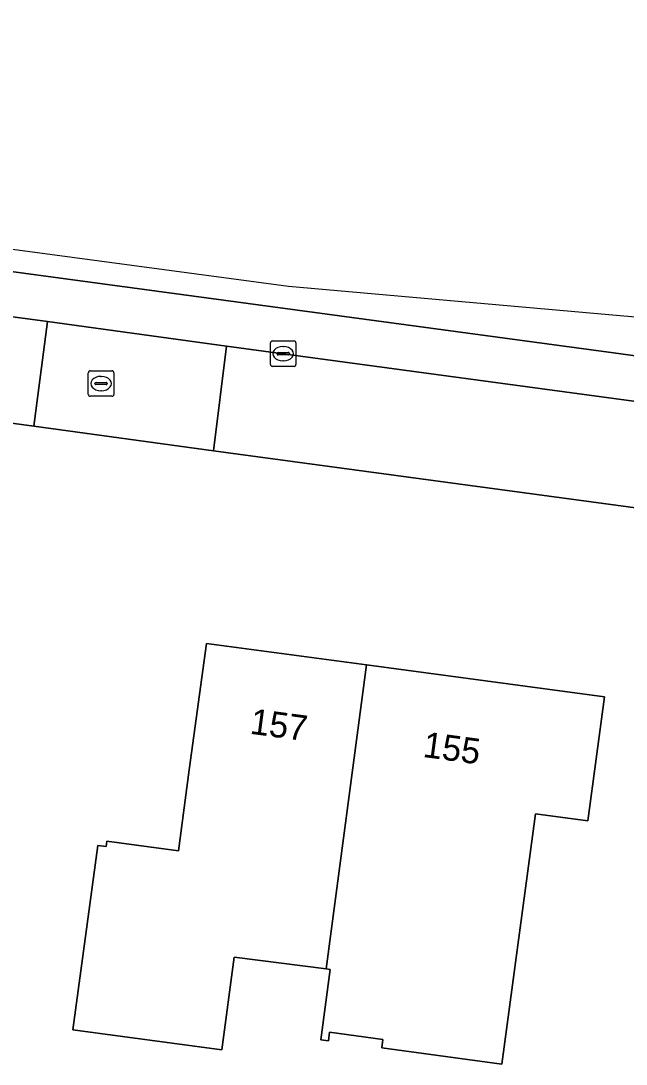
# Model space of a CAD drawing. Extents: x 161483 to 162250, y 379484 to 380833.
# Drawn here: x 162011.75 to 162035.47, y 380752.3 to 380793.17 of the extents above; entities that cross this region are included whole.
import ezdxf

# ---------------------------------------------------------------- set-up
doc = ezdxf.new("R2010")
doc.units = 0
for name, color, linetype in [('IMGEO_Brandkraan', 7, 'Continuous'), ('IMGEO_Erf', 7, 'Continuous'), ('IMGEO_Fietspad_open', 7, 'Continuous'), ('IMGEO_Kolk', 7, 'Continuous'), ('IMGEO_Pand', 7, 'Continuous'), ('IMGEO_Pand_nummerreeks', 7, 'Continuous'), ('IMGEO_Rijbaan_lokaal_gesloten', 7, 'Continuous'), ('IMGEO_Voetpad_open', 7, 'Continuous')]:
    doc.layers.add(name, color=color, linetype=linetype)

msp = doc.modelspace()

# ---------------------------------------------------------------- linework, layer by layer
at = {"layer": 'IMGEO_Brandkraan'}
for p, q in [((162014.398, 380778.539), (162014.398, 380779.391)), ((162014.473, 380779.465), (162015.325, 380779.465)), ((162014.886, 380779.245), (162014.911, 380779.245)), ((162015.399, 380779.391), (162015.399, 380778.539)), ((162014.657, 380778.959), (162014.657, 380778.971)), ((162015.095, 380778.922), (162014.697, 380778.922)), ((162014.7, 380779.008), (162015.098, 380779.008)), ((162015.141, 380778.971), (162015.141, 380778.959)), ((162015.325, 380778.465), (162014.473, 380778.465)), ((162014.909, 380778.685), (162014.884, 380778.685))]:
    msp.add_line(p, q, dxfattribs=at)
for points in [[(162014.398, 380778.539), (162014.398, 380779.391)], [(162014.473, 380779.465), (162015.325, 380779.465)], [(162015.399, 380779.391), (162015.399, 380778.539)], [(162015.325, 380778.465), (162014.473, 380778.465)]]:
    msp.add_lwpolyline(points, dxfattribs=at)
for centre, radius, start, end in [((162014.475, 380779.389), 0.0765, 91.552, 178.448), ((162014.475, 380779.389), 0.0765, 91.552, 178.448), ((162015.323, 380779.389), 0.0765, 1.552, 88.448), ((162015.323, 380779.389), 0.0765, 1.552, 88.448), ((162014.697, 380778.968), 0.0403, 85.8775, 175.7526), ((162014.694, 380778.958), 0.0366, 178.938, 274.7102), ((162015.098, 380778.965), 0.043, 264.8664, 352.4533), ((162015.102, 380778.97), 0.0386, 1.7309, 96.639), ((162014.475, 380778.541), 0.0765, 181.552, 268.448), ((162014.475, 380778.541), 0.0765, 181.552, 268.448), ((162015.323, 380778.541), 0.0765, 271.552, 358.448), ((162015.323, 380778.541), 0.0765, 271.552, 358.448)]:
    msp.add_arc(centre, radius, start, end, dxfattribs=at)
for centre, major_axis, ratio, start_param, end_param in [((162014.885, 380778.965), (-0.387, 0.002), 0.722429, 4.712389, 7.853982), ((162014.91, 380778.965), (-0.39, 0.002), 0.717154, 1.570796, 4.712389)]:
    msp.add_ellipse(centre, major_axis=major_axis, ratio=ratio, start_param=start_param, end_param=end_param, dxfattribs=at)
at = {"layer": 'IMGEO_Erf'}
msp.add_lwpolyline([(162036.037, 380774.07), (162019.302, 380776.332), (162012.257, 380777.298), (162000, 380778.954), (161998.504, 380779.156), (161990.667, 380780.226), (161973.686, 380782.502), (161969.852, 380783.064), (161964.78, 380783.711), (161960.584, 380784.268), (161952.345, 380785.378), (161947.776, 380785.993), (161943.772, 380786.523)], dxfattribs=at)
msp.add_lwpolyline([(162019.024, 380768.784), (162025.294, 380767.942), (162034.627, 380766.69), (162033.971, 380761.828), (162031.92, 380762.105), (162030.596, 380752.302), (162025.897, 380752.936), (162025.942, 380753.273), (162023.851, 380753.555), (162023.806, 380753.218), (162023.509, 380753.258), (162023.868, 380756.015), (162023.719, 380756.034), (162020.116, 380756.497), (162019.625, 380752.86), (162013.794, 380753.648), (162014.77, 380760.869), (162015.097, 380760.825), (162015.125, 380761.033), (162017.926, 380760.655), (162018.355, 380763.83)], close=True, dxfattribs=at)
at = {"layer": 'IMGEO_Fietspad_open'}
for points in [[(162082, 380773.982), (162090.414, 380772.833), (162103.563, 380771.053), (162105.995, 380770.702), (162108.893, 380770.206), (162109.295, 380770.138), (162113.227, 380769.38), (162121.37, 380767.728), (162122.685, 380767.488), (162126.662, 380766.696), (162139.522, 380764.129), (162139.7, 380764.105), (162139.976, 380766.161), (162138.618, 380766.344), (162118.907, 380770.062), (162108.19, 380772.217), (162093.056, 380774.264), (162086.162, 380775.288), (162081.643, 380775.785), (162056.903, 380777.191), (162056.354, 380777.224), (162034.971, 380780.165), (161944.816, 380792.342)], [(161944.345, 380790.629), (161948.316, 380790.073), (161952.821, 380789.486), (161954.565, 380789.259), (161961.171, 380788.373), (161965.375, 380787.789), (161970.49, 380787.09), (161974.247, 380786.595), (161980.364, 380785.76), (161991.175, 380784.302), (161999.086, 380783.254), (162000, 380783.12), (162000.682, 380783.02), (162012.803, 380781.393), (162019.811, 380780.436), (162038.375, 380777.918), (162038.596, 380777.914), (162038.753, 380777.893), (162054.874, 380775.706), (162056.107, 380775.55), (162056.331, 380775.531)]]:
    msp.add_lwpolyline(points, dxfattribs=at)
at = {"layer": 'IMGEO_Kolk'}
for p, q in [((162021.533, 380779.708), (162021.533, 380780.56)), ((162021.608, 380780.634), (162022.46, 380780.634)), ((162022.021, 380780.414), (162022.046, 380780.414)), ((162022.534, 380780.56), (162022.534, 380779.708)), ((162021.792, 380780.128), (162021.792, 380780.14)), ((162022.23, 380780.091), (162021.832, 380780.091)), ((162021.835, 380780.177), (162022.233, 380780.177)), ((162022.276, 380780.14), (162022.276, 380780.128)), ((162022.46, 380779.634), (162021.608, 380779.634)), ((162022.044, 380779.854), (162022.019, 380779.854))]:
    msp.add_line(p, q, dxfattribs=at)
for points in [[(162021.533, 380779.708), (162021.533, 380780.56)], [(162021.608, 380780.634), (162022.46, 380780.634)], [(162022.534, 380780.56), (162022.534, 380779.708)], [(162022.46, 380779.634), (162021.608, 380779.634)]]:
    msp.add_lwpolyline(points, dxfattribs=at)
for centre, radius, start, end in [((162021.61, 380780.558), 0.0765, 91.552, 178.448), ((162021.61, 380780.558), 0.0765, 91.552, 178.448), ((162022.458, 380780.558), 0.0765, 1.552, 88.448), ((162022.458, 380780.558), 0.0765, 1.552, 88.448), ((162021.832, 380780.137), 0.0403, 85.8775, 175.7526), ((162021.829, 380780.127), 0.0366, 178.938, 274.7102), ((162022.233, 380780.134), 0.043, 264.8664, 352.4533), ((162022.237, 380780.139), 0.0386, 1.7309, 96.639), ((162021.61, 380779.71), 0.0765, 181.552, 268.448), ((162021.61, 380779.71), 0.0765, 181.552, 268.448), ((162022.458, 380779.71), 0.0765, 271.552, 358.448), ((162022.458, 380779.71), 0.0765, 271.552, 358.448)]:
    msp.add_arc(centre, radius, start, end, dxfattribs=at)
for centre, major_axis, ratio, start_param, end_param in [((162022.02, 380780.134), (-0.387, 0.002), 0.722429, 4.712389, 7.853982), ((162022.045, 380780.134), (-0.39, 0.002), 0.717154, 1.570796, 4.712389)]:
    msp.add_ellipse(centre, major_axis=major_axis, ratio=ratio, start_param=start_param, end_param=end_param, dxfattribs=at)
at = {"layer": 'IMGEO_Pand'}
for points in [[(162025.294, 380767.942), (162019.024, 380768.784), (162018.355, 380763.83), (162017.926, 380760.655), (162015.125, 380761.033), (162015.097, 380760.825), (162014.77, 380760.869), (162013.794, 380753.648), (162019.625, 380752.86), (162020.116, 380756.497), (162023.719, 380756.034)], [(162023.719, 380756.034), (162023.868, 380756.015), (162023.509, 380753.258), (162023.806, 380753.218), (162023.851, 380753.555), (162025.942, 380753.273), (162025.897, 380752.936), (162030.596, 380752.302), (162031.92, 380762.105), (162033.971, 380761.828), (162034.627, 380766.69), (162025.294, 380767.942)]]:
    msp.add_lwpolyline(points, close=True, dxfattribs=at)
at = {"layer": 'IMGEO_Rijbaan_lokaal_gesloten'}
for points in [[(162235.883, 380761.117), (162225.793, 380762.232), (162195.841, 380761.556), (162155.522, 380766.113), (162152.312, 380766.476), (162100.246, 380775.712), (162094.38, 380775.785), (162063.3, 380779.137), (162022.247, 380782.773), (161914.65, 380797.204), (161859.959, 380804.218), (161826.791, 380811.355), (161807.579, 380816.265), (161765.369, 380823.138), (161719.379, 380829.094), (161719.203, 380827.684), (161722.585, 380827.174), (161725.837, 380826.617)], [(161833.402, 380807.634), (161845.075, 380805.921), (161887.22, 380800.191), (161944.816, 380792.342), (162034.971, 380780.165), (162056.354, 380777.224), (162056.903, 380777.191), (162081.643, 380775.785), (162086.162, 380775.288), (162093.056, 380774.264), (162108.19, 380772.217), (162118.907, 380770.062), (162138.618, 380766.344), (162139.976, 380766.161), (162155.313, 380764.1), (162157.657, 380763.785), (162175.214, 380761.306), (162198.829, 380757.994), (162207.5, 380757.078), (162216.737, 380756.638)]]:
    msp.add_lwpolyline(points, dxfattribs=at)
at = {"layer": 'IMGEO_Voetpad_open'}
for points in [[(162000, 380778.954), (162012.257, 380777.298), (162012.803, 380781.393), (162000.682, 380783.02), (162000, 380783.12), (161999.086, 380783.254), (161998.504, 380779.156)], [(162019.302, 380776.332), (162019.811, 380780.436), (162012.803, 380781.393), (162012.257, 380777.298)]]:
    msp.add_lwpolyline(points, close=True, dxfattribs=at)
msp.add_lwpolyline([(162038.753, 380777.893), (162038.596, 380777.914), (162038.375, 380777.918), (162019.811, 380780.436), (162019.302, 380776.332), (162036.037, 380774.07)], dxfattribs=at)

# ---------------------------------------------------------------- texts
at = {"layer": 'IMGEO_Pand_nummerreeks'}
for s, rotation, p in [('157', 352.3567, (162020.699, 380765.25)), ('155', 352.3563, (162027.476, 380764.34))]:
    msp.add_text(s, height=1, rotation=rotation, dxfattribs=at).set_placement(p)

doc.saveas('drawing.dxf')
